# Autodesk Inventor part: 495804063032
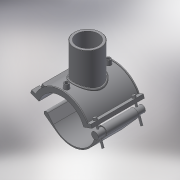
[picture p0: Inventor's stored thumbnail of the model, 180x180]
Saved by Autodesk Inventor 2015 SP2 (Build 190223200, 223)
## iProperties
Created: 2017-07
Part Number: 495804063032
Material: Generic
Description: PLASSON BRANCH SADDLE 63-32
Document SubType Name: Modeling
Designer: KIM
Density: 1 g/cm^3
Appearance: Default
Author: KIM
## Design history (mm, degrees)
derived "495804.ipt"
feature "Solid1::495804.ipt"
feature "Solid2::495804.ipt"
tag "TaggingFeature1"
body "Solid1"
body "Solid2"
other parameters: "d_" = 63, "H_" = 59, "L_" = 118, "d_t" = 6, "d_1" = 32, "H_1" = 49, "d1" = 83, "d148" = 1.575, "d160" = 1.575, "d0" = 63, "d3" = 15.75, "d4" = 118, "d5" = 0, "d6" = 0.1, "d8" = 0, "d19" = 6, "d20" = 6, "d21" = 70.8, "d23" = 0, "d24" = 35.4, "d26" = 0, "d27" = 3, "d28" = 3, "d29" = 3, "d30" = 21, "d31" = 6, "d32" = 0, "d33" = 0, "d34" = 0.6, "d40" = 43.16, "d41" = 35.2, "d43" = 0, "d45" = 0, "d47" = 100.5, "d48" = 32, "d50" = 0, "d70" = 15, "d72" = 0, "d73" = 6, "d75" = 5, "d76" = 0, "d77" = 3.15, "d78" = 61.5, "d79" = 15, "d80" = 47.2, "d82" = 5 deg, "d84" = 4, "d85" = 14, "d86" = 0, "d87" = 3, "d88" = 0, "d89" = 1, "d90" = 1, "d91" = 94.4, "d92" = 0, "d93" = 0.5, "d94" = 33.15789, "d96" = 84.66, "d97" = 2.36, "d98" = 0, "d102" = 0.96, "d103" = 25.6, "d105" = 0, "d109" = -19.66667, "d117" = 0.32, "d120" = 140 deg, "d121" = 24.228, "d122" = 20 deg, "d123" = 166, "d124" = 49.8, "d126" = 0, "d143" = 66.15, "d150" = 11.34, "d159" = 4, "d161" = 1.575, "d162" = 70.8, "d163" = 0, "d167" = 12.6, "d168" = 37.72727, "d173" = 1, "d175" = 31.5, "d176" = 20 deg, "d177" = 4.41, "d180" = 0, "d185" = 38.35, "d186" = 38.35, "d187" = 41.5, "d188" = 6, "d189" = 4.41, "d190" = 0, "d191" = 62.25, "d202" = 0, "d216" = 106.2, "d217" = 0, "d221" = 43.66, "d222" = 4.41, "d223" = 2.646, "d224" = 31.5, "d225" = 2.646, "d227" = 9.072, "d230" = 39.06, "d236" = 20 deg, "d237" = 48.5, "d238" = 20 deg, "d239" = 4.41
